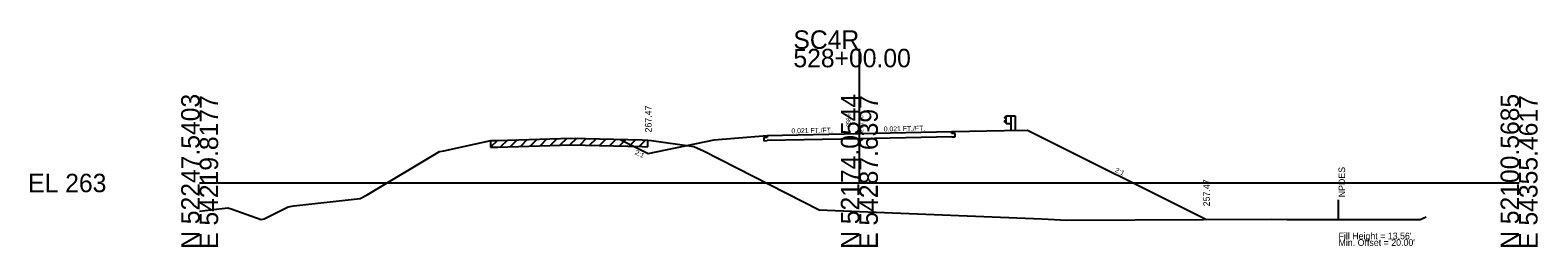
# Model space of a CAD drawing. Extents: x 7498 to 13027, y 90095 to 109625.
# Drawn here: x 9498.3 to 9726.8, y 98095.5 to 98128.4 of the extents above; entities that cross this region are included whole.
import ezdxf

# ---------------------------------------------------------------- set-up
doc = ezdxf.new("R2010")
doc.units = 0
for name, color, linetype in [('Level 10', 7, 'Continuous'), ('Level 11', 7, 'Continuous'), ('Level 12', 7, 'Continuous'), ('Level 24', 7, 'Continuous'), ('Level 32', 7, 'Continuous'), ('Level 33', 7, 'Continuous'), ('Level 50', 7, 'Continuous'), ('Level 55', 7, 'Continuous'), ('Level 59', 7, 'Continuous'), ('Level 6', 7, 'Continuous'), ('Level 60', 7, 'Continuous'), ('Level 61', 7, 'Continuous'), ('Level 63', 7, 'Continuous'), ('Level 7', 7, 'Continuous')]:
    doc.layers.add(name, color=color, linetype=linetype)

msp = doc.modelspace()

# ---------------------------------------------------------------- linework, layer by layer
at = {"layer": 'Level 11'}
for p, q in [((9637.99, 98112.65), (9637.99, 98112.95)), ((9638.49, 98112.66), (9637.99, 98112.65)), ((9638.49, 98112.18), (9638.49, 98112.66)), ((9609.99, 98112.07), (9609.49, 98112.05)), ((9609.49, 98112.05), (9609.49, 98111.57)), ((9609.49, 98111.57), (9609.99, 98111.59)), ((9609.99, 98112.37), (9609.99, 98112.07)), ((9637.99, 98112.17), (9638.49, 98112.18))]:
    msp.add_line(p, q, dxfattribs=at)
at = {"layer": 'Level 12'}
for p, q in [((9623.99, 98111.88), (9609.99, 98111.59)), ((9637.99, 98112.17), (9623.99, 98111.88))]:
    msp.add_line(p, q, dxfattribs=at)
at = {"layer": 'Level 24'}
for p, q in [((9646.26, 98115.29), (9645.99, 98115.09)), ((9645.99, 98115.09), (9645.99, 98115.04)), ((9645.99, 98115.04), (9646.26, 98114.84)), ((9645.99, 98114.52), (9646.26, 98114.72)), ((9646.26, 98114.2), (9646.26, 98115.36)), ((9646.26, 98115.36), (9646.93, 98115.36)), ((9646.93, 98115.36), (9646.93, 98113.13)), ((9646.93, 98115.36), (9647.6, 98115.36)), ((9647.6, 98115.36), (9647.6, 98113.15)), ((9645.99, 98114.47), (9645.99, 98114.52)), ((9646.26, 98114.27), (9645.99, 98114.47)), ((9646.26, 98114.2), (9646.93, 98114.2))]:
    msp.add_line(p, q, dxfattribs=at)
at = {"layer": 'Level 55'}
msp.add_line((9696.62, 98099.62), (9696.62, 98102.62), dxfattribs=at)
at = {"layer": 'Level 59'}
for p, q in [((9609.99, 98112.37), (9623.99, 98112.66)), ((9623.99, 98112.66), (9637.99, 98112.95))]:
    msp.add_line(p, q, dxfattribs=at)
at = {"layer": 'Level 6'}
for p, q in [((9637.99, 98112.95), (9645.99, 98113.11)), ((9645.99, 98113.11), (9649.49, 98113.19)), ((9601.99, 98111.7), (9609.99, 98112.37))]:
    msp.add_line(p, q, dxfattribs=at)
at = {"layer": 'Level 60'}
for p, q in [((9561, 98110.05), (9568.14, 98111.6)), ((9568.14, 98111.6), (9569.12, 98111.62)), ((9569.12, 98111.62), (9580.26, 98111.94)), ((9580.26, 98111.94), (9591.06, 98111.69)), ((9591.06, 98111.69), (9591.95, 98111.67)), ((9591.95, 98111.67), (9592.48, 98111.61)), ((9592.48, 98111.61), (9598.9, 98110.68)), ((9598.9, 98110.68), (9600.37, 98110.02)), ((9549.36, 98103.34), (9560.34, 98109.92)), ((9560.34, 98109.92), (9561, 98110.05)), ((9600.37, 98110.02), (9617.89, 98101.08)), ((9548.33, 98102.8), (9549.36, 98103.34)), ((9523.99, 98100.9), (9528.24, 98101.37)), ((9528.24, 98101.37), (9528.78, 98101.24)), ((9528.78, 98101.24), (9533.33, 98099.6)), ((9533.77, 98099.73), (9537.42, 98101.56)), ((9537.42, 98101.56), (9538.29, 98101.7)), ((9538.29, 98101.7), (9548.33, 98102.8)), ((9617.89, 98101.08), (9623.99, 98100.83)), ((9533.33, 98099.6), (9533.77, 98099.73)), ((9623.99, 98100.83), (9651.67, 98099.71)), ((9651.67, 98099.71), (9655.46, 98099.5)), ((9655.46, 98099.5), (9686.42, 98099.68)), ((9686.42, 98099.68), (9688.85, 98099.64)), ((9688.85, 98099.64), (9707, 98099.64)), ((9707, 98099.64), (9709.02, 98099.64)), ((9709.02, 98099.64), (9709.93, 98100.04))]:
    msp.add_line(p, q, dxfattribs=at)
at = {"layer": 'Level 61'}
for p, q in [((9569.13, 98111.62), (9568.1, 98110.59)), ((9568.1, 98111.59), (9568.1, 98110.59)), ((9568.1, 98110.59), (9568.14, 98110.6)), ((9568.14, 98110.6), (9569.12, 98110.62)), ((9569.12, 98110.62), (9580.26, 98110.94)), ((9570.63, 98111.67), (9569.6, 98110.64)), ((9572.13, 98111.71), (9571.1, 98110.68)), ((9573.63, 98111.75), (9572.6, 98110.72)), ((9575.13, 98111.8), (9574.1, 98110.77)), ((9576.63, 98111.84), (9575.6, 98110.81)), ((9578.13, 98111.88), (9577.1, 98110.85)), ((9579.63, 98111.93), (9578.6, 98110.9)), ((9581.09, 98111.92), (9580.1, 98110.94)), ((9580.26, 98110.94), (9591.06, 98110.69)), ((9582.58, 98111.89), (9581.6, 98110.91)), ((9584.08, 98111.85), (9583.1, 98110.88)), ((9585.58, 98111.82), (9584.6, 98110.84)), ((9587.08, 98111.78), (9586.1, 98110.8)), ((9588.58, 98111.74), (9587.6, 98110.77)), ((9590.08, 98111.71), (9589.1, 98110.73)), ((9591.59, 98111.68), (9590.6, 98110.7)), ((9591.06, 98110.69), (9591.95, 98110.67)), ((9591.95, 98110.67), (9591.95, 98111.67)), ((9591.95, 98110.67), (9591.95, 98110.67))]:
    msp.add_line(p, q, dxfattribs=at)
at = {"layer": 'Level 63'}
for p, q in [((9623.99, 98105.16), (9623.99, 98125.52)), ((9523.99, 98105.16), (9623.99, 98105.16)), ((9623.99, 98105.16), (9723.99, 98105.16))]:
    msp.add_line(p, q, dxfattribs=at)
at = {"layer": 'Level 7'}
for p, q in [((9649.49, 98113.19), (9676.62, 98099.62)), ((9587.71, 98111.77), (9591.99, 98109.62)), ((9591.99, 98109.62), (9601.99, 98111.7))]:
    msp.add_line(p, q, dxfattribs=at)

# ---------------------------------------------------------------- texts
at = {"layer": 'Level 10'}
msp.add_text('258.67', height=0.6, rotation=90, dxfattribs=at).set_placement((9622.63, 98113.66))
at = {"layer": 'Level 32'}
for s, rotation, p in [('0.021 FT./FT.', 1.1916, (9613.7, 98112.69)), ('0.021 FT./FT.', 1.1916, (9627.7, 98112.98)), ('2:1', 333.435, (9589.89, 98109.55)), ('2:1', 333.435, (9662.66, 98106.88))]:
    msp.add_text(s, height=0.75, rotation=rotation, dxfattribs=at).set_placement(p)
at = {"layer": 'Level 33'}
for s, p in [('267.47', (9592.49, 98112.83)), ('257.47', (9677.12, 98101.62))]:
    msp.add_text(s, height=1, rotation=90, dxfattribs=at).set_placement(p)
at = {"layer": 'Level 50'}
msp.add_text(' NPDES', height=1, rotation=90, dxfattribs=at).set_placement((9697.62, 98102.62))
for s, p in [("Fill Height = 13.56' ", (9696.62, 98096.62)), ("Min. Offset = 20.00' ", (9696.62, 98095.62))]:
    msp.add_text(s, height=1, dxfattribs=at).set_placement(p)
at = {"layer": 'Level 59'}
msp.add_text(' 270.50', height=0.6, rotation=90, dxfattribs=at).set_placement((9624.59, 98112.66))
at = {"layer": 'Level 63'}
for s, p in [('SC4R', (9613.99, 98125.52)), ('528+00.00', (9613.99, 98122.72)), ('EL 263', (9497.99, 98103.76))]:
    msp.add_text(s, height=2.8, dxfattribs=at).set_placement(p)
for s, p in [('N 52247.5403', (9523.99, 98095.16)), ('E 54219.8177', (9526.79, 98095.16)), ('N 52174.0544', (9623.99, 98095.16)), ('E 54287.6397', (9626.79, 98095.16)), ('N 52100.5685', (9723.99, 98095.16)), ('E 54355.4617', (9726.79, 98095.16))]:
    msp.add_text(s, height=2.8, rotation=90, dxfattribs=at).set_placement(p)

doc.saveas('drawing.dxf')
